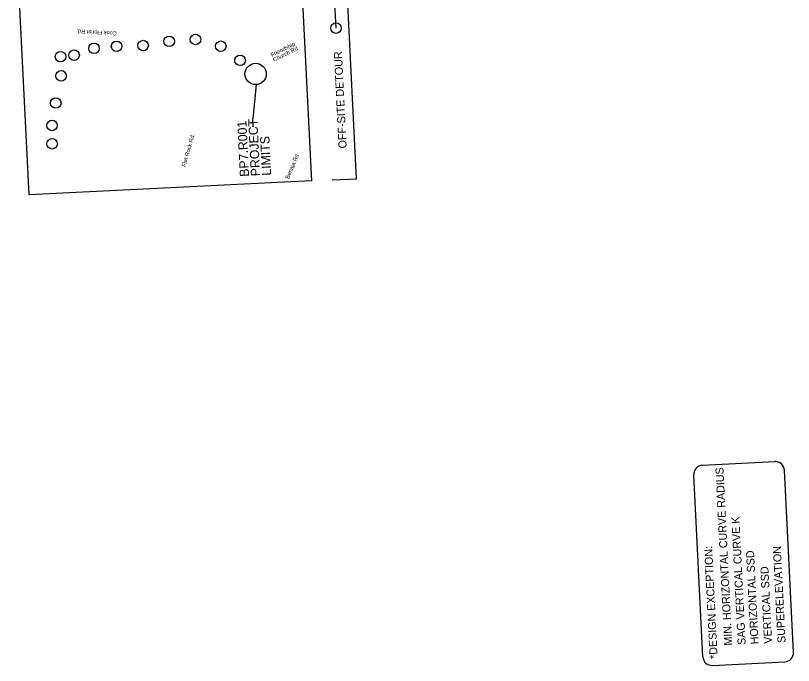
# Model space of a CAD drawing. Extents: x 1805231 to 1809482, y 908883 to 918297.
# Drawn here: x 1805232 to 1809482, y 908883 to 912434 of the extents above; entities that cross this region are included whole.
import ezdxf

# ---------------------------------------------------------------- set-up
doc = ezdxf.new("R2010")
doc.units = 0
for name, color, linetype in [('Default', 7, 'Continuous'), ('Matchline Text', 7, 'Continuous'), ('Old_Level_18', 7, 'Continuous'), ('Old_Level_38', 7, 'Continuous'), ('Old_Level_40', 7, 'Continuous'), ('Prop DSN Text', 7, 'Continuous'), ('Scratch_Level_0', 7, 'Continuous')]:
    doc.layers.add(name, color=color, linetype=linetype)

msp = doc.modelspace()

# ---------------------------------------------------------------- linework, layer by layer
at = {"layer": 'Old_Level_18'}
for p, q in [((1808985.2, 909977.6), (1809380.2, 909997.3)), ((1809482, 908955.5), (1809432.6, 909949.8)), ((1808987.1, 908930.9), (1808937.7, 909925.2)), ((1809039.5, 908883.4), (1809434.5, 908903))]:
    msp.add_line(p, q, dxfattribs=at)
for centre, start, end in [((1809382.7, 909947.3), 2.8422, 92.8422), ((1808987.7, 909927.7), 92.8422, 182.8422), ((1809037, 908933.4), 182.8422, 272.8422), ((1809432, 908953), 272.8422, 2.8422)]:
    msp.add_arc(centre, 50, start, end, dxfattribs=at)
at = {"layer": 'Old_Level_40'}
for p, q in [((1807095.1, 911542.9), (1807012.5, 913208)), ((1806546.6, 912057.2), (1806528.7, 911869.3)), ((1806530.8, 911825.9), (1806528.7, 911869.3)), ((1806962.6, 911536.3), (1807095.1, 911542.9))]:
    msp.add_line(p, q, dxfattribs=at)
msp.add_circle((1806543.7, 912115.3), 58.2, dxfattribs=at)
at = {"layer": 'Prop DSN Text'}
msp.add_line((1806982.8, 912365.7), (1806953, 912965), dxfattribs=at)
for centre in [(1806982.8, 912365.7), (1806071.2, 912293.6), (1806215.2, 912303.8), (1805660.6, 912255), (1805783.9, 912266.3), (1805928.6, 912270.4), (1806353, 912266.6), (1805478, 912209.3), (1805551.9, 912217.8), (1806458.7, 912189.3), (1805480.6, 912104.8), (1805451.5, 911956.2), (1805431.4, 911834), (1805431.8, 911733.6)]:
    msp.add_circle(centre, 28.8, dxfattribs=at)
at = {"layer": 'Scratch_Level_0'}
msp.add_lwpolyline([(1805306.3, 911454), (1805232, 912951), (1805398.3, 912959.3), (1805389.9, 913127.5), (1806765.8, 913195.8), (1806848.5, 911530.6)], close=True, dxfattribs=at)

# ---------------------------------------------------------------- texts
at = {"layer": 'Default'}
for s, rotation, p in [('Cook Florist Rd.', 176.9058, (1805785.5, 912346.9)), ('Flat Rock Rd.', 74.0927, (1806160.3, 911605.7))]:
    msp.add_text(s, height=22.242, rotation=rotation, dxfattribs=at).set_placement(p)
at = {"layer": 'Matchline Text'}
for s, rotation, p in [('Friendship', 26.4857, (1806633.3, 912207.9)), ('Church Rd', 26.4857, (1806645.4, 912181.6)), ('Benaja Rd', 67.1693, (1806724.9, 911539.3))]:
    msp.add_text(s, height=22.24, rotation=rotation, dxfattribs=at).set_placement(p)
at = {"layer": 'Old_Level_38'}
for s, p in [('MIN. HORIZONTAL CURVE RADIUS', (1809147.5, 908992.8)), ('SAG VERTICAL CURVE K', (1809221.3, 908996.4)), ('*DESIGN EXCEPTION: ', (1809068.2, 908920.1)), ('SUPERELEVATION', (1809439.3, 909007.3)), ('HORIZONTAL SSD', (1809291.7, 908999.9)), ('VERTICAL SSD', (1809365.5, 909003.6))]:
    msp.add_text(s, height=43.751, rotation=92.8372, dxfattribs=at).set_placement(p)
at = {"layer": 'Old_Level_40'}
for s, p in [('BP7.R001', (1806508.2, 911554.5)), ('PROJECT', (1806568.5, 911557.5)), ('LIMITS', (1806628.8, 911560.5))]:
    msp.add_text(s, height=50.29, rotation=92.8424, dxfattribs=at).set_placement(p)
at = {"layer": 'Prop DSN Text'}
msp.add_text('OFF-SITE DETOUR', height=43.846, rotation=92.8422, dxfattribs=at).set_placement((1807041.1, 911709.3))

doc.saveas('drawing.dxf')
